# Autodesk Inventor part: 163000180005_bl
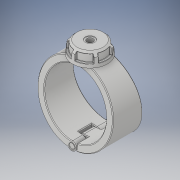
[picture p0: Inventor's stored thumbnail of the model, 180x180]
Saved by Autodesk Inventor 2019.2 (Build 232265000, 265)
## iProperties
Created: 2022-02
Part Number: 163000180005_bl
Material: Generic
Description: Plassadle Threaded 180x1/2''
Document SubType Name: Modeling
Designer: comp2
Density: 1 g/cm^3
Appearance: Default
Author: comp2
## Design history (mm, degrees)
derived "16300.ipt"
feature "Solid1::16300.ipt" dims "ScaleForDerivedMember" = 10
feature "Solid2::16300.ipt" dims "ScaleForDerivedMember" = 10
feature "Solid3::16300.ipt" dims "ScaleForDerivedMember" = 10
feature "Solid4::16300.ipt" dims "ScaleForDerivedMember" = 10
tag "TaggingFeature1"
body "Solid1"
body "Solid2"
body "Solid3"
body "Solid4"
other parameters: "d7" = 209 [user parameter], "d8" = 85 deg [user parameter], "d9" = 45 deg [user parameter], "d10" = 102 [user parameter], "d11" = 49 [user parameter], "d12" = 25.27 [user parameter], "d13" = 42.84 [user parameter], "d14" = 27.9465 [user parameter], "d42" = 4 [user parameter], "d49" = 4.4 [user parameter], "d51" = 0 [user parameter], "d52" = 28 [user parameter], "d53" = 121 [user parameter], "d54" = 38.5 [user parameter], "d55" = 0 [user parameter], "d56" = 22 [user parameter], "d57" = 22 [user parameter], "d59" = 0 [user parameter], "d61" = 0 [user parameter], "d62" = 38.5 [user parameter], "d63" = 0 [user parameter], "d65" = 0 [user parameter], "d67" = 0 [user parameter], "d69" = 0 [user parameter], "d70" = 1 [user parameter], "d71" = 105.6 [user parameter], "d72" = 0 [user parameter], "d73" = 2 [user parameter], "d78" = 86.7 [user parameter], "d79" = 5.1 [user parameter], "d80" = 60 deg [user parameter], "d81" = 5.1 [user parameter], "d84" = 0 [user parameter], "d85" = 1 [user parameter], "d87" = 360 deg [user parameter], "d122" = 49 [user parameter], "d124" = 42.80128 [user parameter], "d125" = 1.805 [user parameter], "d127" = 255 [user parameter], "d129" = 18.631 [user parameter], "d130" = 15.83635 [user parameter], "d131" = 31.85 [user parameter], "d132" = 45 deg [user parameter], "d133" = 22.295 [user parameter], "d134" = 9.3155 [user parameter], "d136" = 0 [user parameter], "d138" = 0 [user parameter], "d1" = 25 [user parameter], "E_" = 54 [user parameter], "E1" = 102 [user parameter], "H1" = 255 [user parameter], "H2" = 49 [user parameter], "H3" = 78 [user parameter], "H_costum" = 49 [user parameter], "Rp" = 18.631 [user parameter], "d128" = 36.1 [user parameter]
